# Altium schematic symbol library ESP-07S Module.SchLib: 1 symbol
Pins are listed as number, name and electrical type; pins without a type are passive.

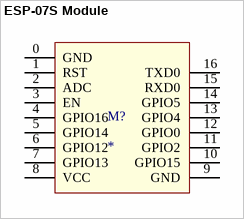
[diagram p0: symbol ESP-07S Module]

## ESP-07S Module
designator M?
ESP-07S Module
footprint ESP-07S Module
pins: 0 GND, 1 RST, 2 ADC, 3 EN, 4 GPIO16, 5 GPIO14, 6 GPIO12, 7 GPIO13, 8 VCC, 9 GND, 10 GPIO15, 11 GPIO2, 12 GPIO0, 13 GPIO4, 14 GPIO5, 15 RXD0, 16 TXD0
